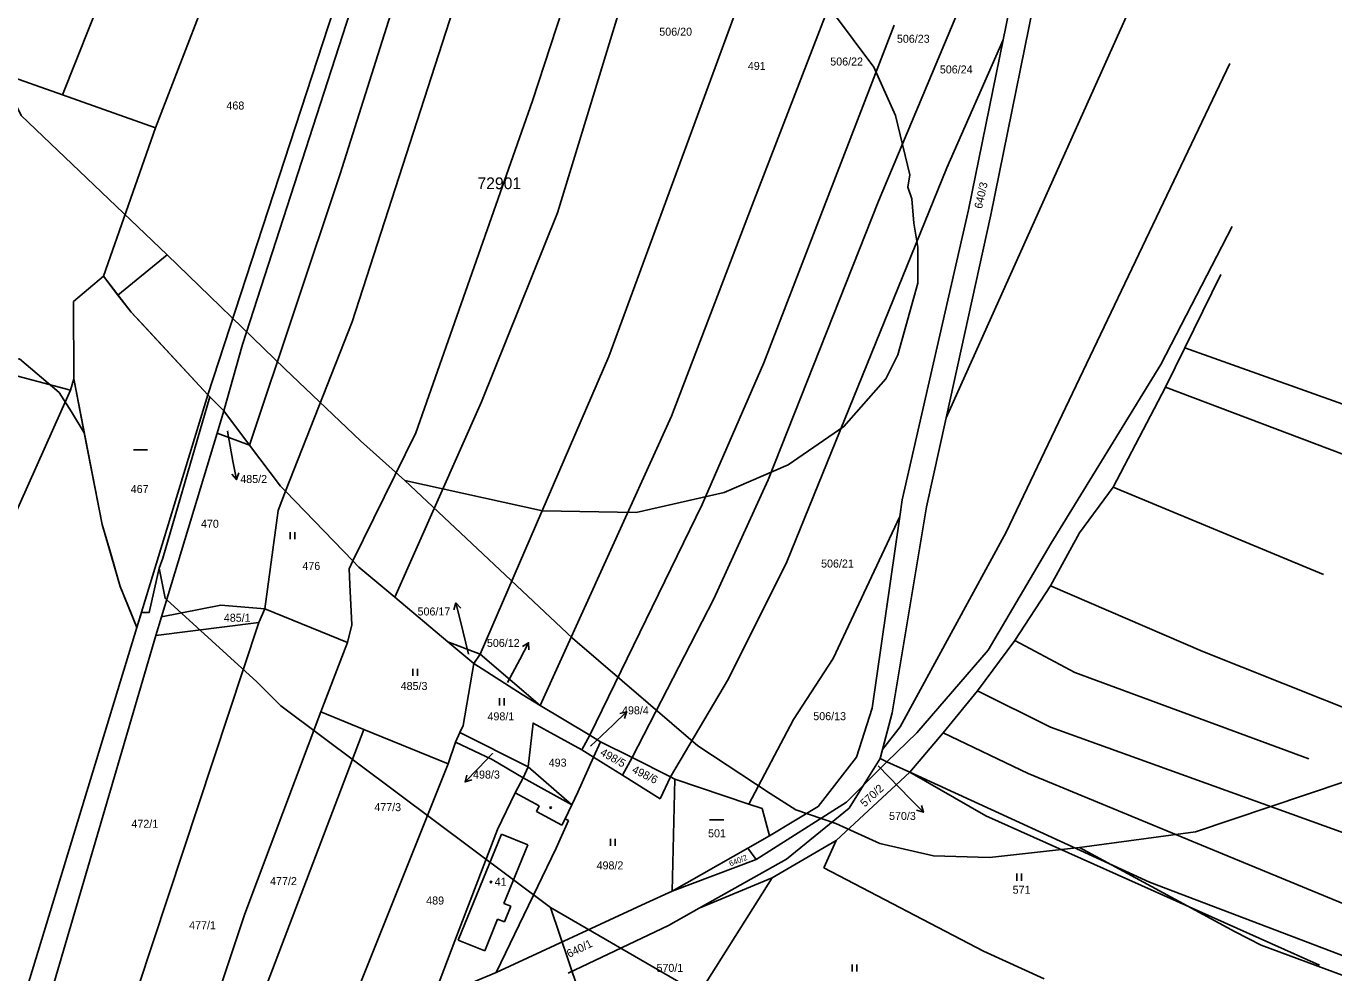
# Model space of a CAD drawing. Extents: x -743888 to -742027, y -1128394 to -1126768.
# Drawn here: x -742758.2 to -742480.3, y -1127090.1 to -1126888.9 of the extents above; entities that cross this region are included whole.
import ezdxf

# ---------------------------------------------------------------- set-up
doc = ezdxf.new("R2010")
doc.units = 0
for name, color, linetype in [('Vrstva 1', 7, 'Continuous'), ('Vrstva 16', 7, 'Continuous'), ('Vrstva 18', 7, 'Continuous'), ('Vrstva 19', 7, 'Continuous'), ('Vrstva 25', 7, 'Continuous'), ('Vrstva 3', 7, 'Continuous'), ('Vrstva 37', 7, 'Continuous'), ('Vrstva 4', 7, 'Continuous'), ('Vrstva 52', 7, 'Continuous'), ('Vrstva 53', 7, 'Continuous'), ('Vrstva 6', 7, 'Continuous')]:
    doc.layers.add(name, color=color, linetype=linetype)

msp = doc.modelspace()

# ---------------------------------------------------------------- linework, layer by layer
at = {"layer": 'Vrstva 1'}
for points in [[(-742550.57, -1126891.8), (-742539.32, -1126836.74)], [(-742553.22, -1126928.98), (-742541.56, -1126871.36)], [(-742557.96, -1126927.95), (-742550.57, -1126891.8)], [(-742572.06, -1126989.56), (-742557.96, -1126927.95)], [(-742562.72, -1126972.14), (-742553.22, -1126928.98)], [(-742748.16, -1126947.44), (-742741.76, -1126942.06)], [(-742741.76, -1126942.06), (-742735.91, -1126949.7)], [(-742748.16, -1126947.44), (-742748.07, -1126963.89)], [(-742735.91, -1126949.7), (-742719.6, -1126967.23)], [(-742748.07, -1126963.89), (-742742.04, -1126994.82)], [(-742734.68, -1127016.73), (-742719.6, -1126967.23)], [(-742719.6, -1126967.23), (-742716.17, -1126970.68)], [(-742717.6, -1126975.4), (-742716.17, -1126970.68)], [(-742716.17, -1126970.68), (-742710.71, -1126977.95)], [(-742566.88, -1126991.03), (-742562.72, -1126972.14)], [(-742729.41, -1127014.42), (-742717.6, -1126975.4)], [(-742710.71, -1126977.95), (-742704.16, -1126986.66)], [(-742704.16, -1126986.66), (-742703.1, -1126987.76)], [(-742703.1, -1126987.76), (-742688.81, -1127002.53)], [(-742572.58, -1126993.14), (-742572.06, -1126989.56)], [(-742574.16, -1127034.85), (-742566.88, -1126991.03)], [(-742742.04, -1126994.82), (-742738.19, -1127008)], [(-742578.46, -1127033.87), (-742572.58, -1126993.14)], [(-742688.81, -1127002.53), (-742687.53, -1127003.86)], [(-742687.53, -1127003.86), (-742679.87, -1127010.3)], [(-742738.19, -1127008), (-742734.68, -1127016.73)], [(-742679.87, -1127010.3), (-742668.63, -1127019.74)], [(-742730.63, -1127018.43), (-742729.41, -1127014.42)], [(-742781.25, -1127169.22), (-742734.68, -1127016.73)], [(-742737.64, -1127102.99), (-742708.78, -1127015.67)], [(-742753.9, -1127097.67), (-742730.63, -1127018.43)], [(-742668.63, -1127019.74), (-742663.1, -1127024.39)], [(-742663.1, -1127024.39), (-742652.83, -1127030.94)], [(-742652.83, -1127030.94), (-742648.95, -1127033.28)], [(-742648.95, -1127033.28), (-742638.43, -1127039.61)], [(-742581.78, -1127044.3), (-742578.46, -1127033.87)], [(-742576.22, -1127042.62), (-742574.16, -1127034.85)], [(-742651.5, -1127046.32), (-742650.49, -1127037.02), (-742640.1, -1127042.71)], [(-742638.43, -1127039.61), (-742636.14, -1127040.99)], [(-742668.53, -1127045.71), (-742666.98, -1127041.09)], [(-742666.98, -1127041.09), (-742659.18, -1127044.79)], [(-742637.62, -1127044.26), (-742636.14, -1127040.99)], [(-742636.14, -1127040.99), (-742629.44, -1127044.36)], [(-742659.18, -1127044.79), (-742652.6, -1127048.7)], [(-742641, -1127051.72), (-742637.62, -1127044.26)], [(-742640.1, -1127042.71), (-742637.62, -1127044.26)], [(-742637.62, -1127044.26), (-742631.47, -1127048.12)], [(-742631.47, -1127048.12), (-742629.44, -1127044.36)], [(-742629.44, -1127044.36), (-742621.26, -1127048.47)], [(-742589.93, -1127054.79), (-742581.78, -1127044.3)], [(-742580.29, -1127050.24), (-742576.74, -1127044.58)], [(-742576.74, -1127044.58), (-742576.22, -1127042.62)], [(-742576.74, -1127044.58), (-742575.31, -1127045.24)], [(-742575.31, -1127045.24), (-742570.42, -1127047.48)], [(-742692.49, -1127105.57), (-742668.53, -1127045.71)], [(-742652.6, -1127048.7), (-742651.5, -1127046.32)], [(-742570.42, -1127047.48), (-742519.53, -1127070.81)], [(-742654.28, -1127051.82), (-742652.6, -1127048.7)], [(-742621.26, -1127048.47), (-742620.33, -1127048.94)], [(-742620.96, -1127072.73), (-742620.33, -1127048.94)], [(-742620.33, -1127048.94), (-742604.64, -1127054.26)], [(-742583.33, -1127055.08), (-742580.29, -1127050.24)], [(-742658.01, -1127059.67), (-742654.28, -1127051.82)], [(-742642.23, -1127054.43), (-742641, -1127051.72)], [(-742643.7, -1127057.4), (-742642.23, -1127054.43)], [(-742604.64, -1127054.26), (-742601.82, -1127055.21)], [(-742601.82, -1127055.21), (-742600.22, -1127061)], [(-742600.22, -1127061), (-742589.93, -1127054.79)], [(-742596.61, -1127065.97), (-742583.33, -1127055.08)], [(-742645.55, -1127063.63), (-742642.98, -1127057.75)], [(-742643.7, -1127057.4), (-742642.98, -1127057.75)], [(-742667.08, -1127083.34), (-742658.01, -1127059.67)], [(-742604.82, -1127063.6), (-742600.22, -1127061)], [(-742658.33, -1127090.03), (-742645.55, -1127063.63)], [(-742620.96, -1127072.73), (-742604.82, -1127063.6)], [(-742604.82, -1127063.6), (-742603.07, -1127066.02)], [(-742603.07, -1127066.02), (-742620.96, -1127072.73)], [(-742615.18, -1127076.38), (-742596.61, -1127065.97)], [(-742626.53, -1127075.31), (-742620.96, -1127072.73)], [(-742519.53, -1127070.81), (-742452.64, -1127096.27)], [(-742658.33, -1127090.03), (-742626.53, -1127075.31)], [(-742621.7, -1127080.04), (-742615.18, -1127076.38)], [(-742643.05, -1127090.21), (-742621.7, -1127080.04)], [(-742671.78, -1127095.63), (-742667.08, -1127083.34)], [(-742663.55, -1127092.23), (-742658.33, -1127090.03)]]:
    msp.add_lwpolyline(points, dxfattribs=at)
at = {"layer": 'Vrstva 16'}
for p, q in [((-742713.02, -1126983.87), (-742713.51, -1126985.28)), ((-742667.31, -1127012.93), (-742666.89, -1127011.49)), ((-742652.71, -1127020.75), (-742651.44, -1127019.95)), ((-742632.06, -1127034.98), (-742630.6, -1127034.63)), ((-742663.49, -1127049.12), (-742664.93, -1127049.54)), ((-742567.92, -1127054.52), (-742567.55, -1127055.98))]:
    msp.add_line(p, q, dxfattribs=at)
for points in [[(-742715.45, -1126974.96), (-742714.25, -1126981.35)], [(-742714.25, -1126981.35), (-742713.51, -1126985.28), (-742714.49, -1126984.14)], [(-742665.94, -1127015.37), (-742666.89, -1127011.49), (-742665.85, -1127012.57)], [(-742664.21, -1127022.41), (-742665.94, -1127015.37)], [(-742653.31, -1127023.49), (-742651.44, -1127019.95), (-742651.39, -1127021.45)], [(-742655.92, -1127028.43), (-742653.31, -1127023.49)], [(-742633.5, -1127037.38), (-742630.6, -1127034.63), (-742631.03, -1127036.06)], [(-742638.3, -1127041.94), (-742633.5, -1127037.38)], [(-742659.09, -1127043.5), (-742662.15, -1127046.66)], [(-742662.15, -1127046.66), (-742664.93, -1127049.54), (-742664.57, -1127048.08)], [(-742577.15, -1127046.1), (-742570.34, -1127053.11)], [(-742570.34, -1127053.11), (-742567.55, -1127055.98), (-742569, -1127055.57)]]:
    msp.add_lwpolyline(points, dxfattribs=at)
at = {"layer": 'Vrstva 25'}
for p, q in [((-742735.42, -1126978.93), (-742732.42, -1126978.93)), ((-742702.1, -1126996.47), (-742702.1, -1126997.97)), ((-742701.1, -1126997.97), (-742701.1, -1126996.47)), ((-742676.04, -1127025.47), (-742676.04, -1127026.97)), ((-742675.04, -1127026.97), (-742675.04, -1127025.47)), ((-742657.62, -1127031.76), (-742657.62, -1127033.26)), ((-742656.62, -1127033.26), (-742656.62, -1127031.76)), ((-742612.97, -1127057.56), (-742609.97, -1127057.56)), ((-742634.03, -1127061.61), (-742634.03, -1127063.11)), ((-742633.03, -1127063.11), (-742633.03, -1127061.61)), ((-742547.68, -1127069.03), (-742547.68, -1127070.53)), ((-742546.68, -1127070.53), (-742546.68, -1127069.03)), ((-742582.66, -1127088.31), (-742582.66, -1127089.81)), ((-742581.66, -1127089.81), (-742581.66, -1127088.31))]:
    msp.add_line(p, q, dxfattribs=at)
for centre in [(-742646.76, -1127055.01), (-742659.41, -1127070.82)]:
    msp.add_circle(centre, 0.175, dxfattribs=at)
at = {"layer": 'Vrstva 3'}
for points in [[(-742666.37, -1127083.14), (-742657.21, -1127060.61)], [(-742657.21, -1127060.61), (-742651.6, -1127062.89)], [(-742656.67, -1127075.36), (-742651.6, -1127062.89)], [(-742656.67, -1127075.36), (-742655.24, -1127075.94)], [(-742656.59, -1127079.28), (-742655.24, -1127075.94)], [(-742660.76, -1127085.42), (-742658.03, -1127078.7)], [(-742658.03, -1127078.7), (-742656.59, -1127079.28)], [(-742666.37, -1127083.14), (-742660.76, -1127085.42)]]:
    msp.add_lwpolyline(points, dxfattribs=at)
at = {"layer": 'Vrstva 37'}
msp.add_circle((-742659.41, -1127070.82), 0.175, dxfattribs=at)
at = {"layer": 'Vrstva 4'}
for points in [[(-742652.6, -1127048.7), (-742642.23, -1127054.43)], [(-742654.28, -1127051.82), (-742649.19, -1127054.59)], [(-742649.73, -1127055.83), (-742649.19, -1127054.59)], [(-742649.73, -1127055.83), (-742644.34, -1127058.7)], [(-742644.34, -1127058.7), (-742643.7, -1127057.4)], [(-742666.37, -1127083.14), (-742657.21, -1127060.61)], [(-742657.21, -1127060.61), (-742651.6, -1127062.89)], [(-742656.67, -1127075.36), (-742651.6, -1127062.89)], [(-742656.67, -1127075.36), (-742655.24, -1127075.94)], [(-742656.59, -1127079.28), (-742655.24, -1127075.94)], [(-742660.76, -1127085.42), (-742658.03, -1127078.7)], [(-742658.03, -1127078.7), (-742656.59, -1127079.28)], [(-742666.37, -1127083.14), (-742660.76, -1127085.42)]]:
    msp.add_lwpolyline(points, dxfattribs=at)
at = {"layer": 'Vrstva 52'}
for points in [[(-742842.63, -1126818.77), (-742841.5, -1126820.88), (-742788.06, -1126876), (-742780, -1126884.88), (-742766.88, -1126897.63), (-742760.5, -1126905.25), (-742759.25, -1126907.88), (-742728.25, -1126937.5)], [(-742534.38, -1127063.5), (-742509.75, -1127060.13), (-742446.56, -1127038.88), (-742419, -1127033.38), (-742401.19, -1127030), (-742373.19, -1127022.75), (-742310.38, -1126996.88), (-742279.44, -1126979.13), (-742255.25, -1126963.88), (-742232.75, -1126946), (-742222.56, -1126935.88), (-742215.38, -1126928.13), (-742194.13, -1126902.75), (-742186.06, -1126890), (-742178.44, -1126877.25), (-742171.69, -1126862)], [(-742677.75, -1126985.5), (-742648.5, -1126991.88), (-742628.56, -1126992.25), (-742609.88, -1126988), (-742596.31, -1126982.13), (-742584.44, -1126974), (-742575.56, -1126963.88), (-742573, -1126958.75), (-742568.75, -1126943.5), (-742568.75, -1126935.88), (-742569.56, -1126930.75), (-742570, -1126925.63), (-742570.88, -1126923.13), (-742570.44, -1126920.5), (-742573.44, -1126907.88), (-742578.06, -1126897.63), (-742591.25, -1126879.88)], [(-743062.18, -1126930.43), (-743007.81, -1126932), (-742972.19, -1126931.63), (-742966.69, -1126932), (-742958.19, -1126931.63), (-742925.13, -1126931.13), (-742911.13, -1126930.25), (-742889.44, -1126930.75), (-742864, -1126931.13), (-742834.31, -1126932.38), (-742823.69, -1126934.13), (-742801.63, -1126940.13), (-742784.25, -1126946.38), (-742764.75, -1126955.38), (-742762.63, -1126960), (-742759.63, -1126959.63), (-742751.19, -1126966.75), (-742748.56, -1126970.88), (-742745.84, -1126975.32)], [(-742738.69, -1126946.07), (-742728.25, -1126937.5)], [(-742728.25, -1126937.5), (-742703.25, -1126961.75), (-742687.13, -1126977), (-742677.75, -1126985.5)], [(-742738.69, -1126946.07), (-742741.76, -1126942.06), (-742748.16, -1126947.44), (-742748.07, -1126963.89), (-742747.36, -1126967.52), (-742745.84, -1126975.32)], [(-742738.69, -1126946.07), (-742735.91, -1126949.7), (-742733.65, -1126952.13), (-742719.6, -1126967.23), (-742719.16, -1126967.67), (-742729.13, -1127002), (-742729.94, -1127004.13)], [(-742745.84, -1126975.32), (-742742.04, -1126994.82), (-742740.31, -1127000.74), (-742738.19, -1127008), (-742735.98, -1127013.5), (-742734.68, -1127016.73), (-742733.7, -1127013.5), (-742732.06, -1127013.5), (-742729.94, -1127004.13)], [(-742677.75, -1126985.5), (-742642.13, -1127019), (-742615.44, -1127041.88), (-742600.13, -1127052), (-742594.63, -1127055.5), (-742586.13, -1127058.38), (-742576.81, -1127062.63), (-742565.38, -1127065.25), (-742553.5, -1127065.63), (-742534.38, -1127063.5)], [(-742729.94, -1127004.13), (-742728.69, -1127010.5), (-742728.32, -1127010.83), (-742709.19, -1127028.25), (-742704.06, -1127033.38), (-742646.81, -1127076.25)], [(-742604.64, -1127054.26), (-742601.82, -1127055.21), (-742600.22, -1127061), (-742604.82, -1127063.6), (-742620.96, -1127072.73), (-742620.33, -1127048.94), (-742604.64, -1127054.26)], [(-742534.38, -1127063.5), (-742501.31, -1127081.38), (-742495.75, -1127084.25), (-742470.31, -1127093.63), (-742457.63, -1127097), (-742448.69, -1127099.63), (-742443.63, -1127100.88), (-742352.81, -1127132.25), (-742349.44, -1127134), (-742286.19, -1127157.75), (-742260.75, -1127166.63), (-742199.25, -1127187), (-742185.25, -1127192), (-742145.81, -1127205.25), (-742116.5, -1127212.38), (-742099.13, -1127215), (-742086.38, -1127216.25)], [(-742646.81, -1127076.25), (-742640.88, -1127093.63), (-742639.56, -1127114), (-742642.13, -1127136.88), (-742643.44, -1127139.5), (-742645.13, -1127154.75), (-742647.25, -1127164.88), (-742654.44, -1127183.63), (-742666.31, -1127208.13), (-742674.05, -1127219.73), (-742674.81, -1127220.88), (-742680.75, -1127227.25), (-742677.75, -1127229.38)], [(-742646.81, -1127076.25), (-742612.44, -1127096.13), (-742592.5, -1127106.38), (-742546.69, -1127126.75), (-742505.56, -1127139.5), (-742478.38, -1127150), (-742453.38, -1127158.5), (-742442.31, -1127163.63), (-742435.56, -1127165.75), (-742424.06, -1127170.88), (-742339.69, -1127206.5), (-742305.31, -1127215.88), (-742247.63, -1127232), (-742239.56, -1127234.88), (-742196.25, -1127246), (-742170.81, -1127254), (-742159.38, -1127257.38), (-742097.81, -1127270.5)]]:
    msp.add_lwpolyline(points, dxfattribs=at)
at = {"layer": 'Vrstva 6'}
for points in [[(-742603.91, -1126926.94), (-742554.63, -1126799.18)], [(-742691.49, -1126920.27), (-742659.71, -1126819.94)], [(-742688.91, -1126951.77), (-742648.33, -1126826.13)], [(-742634.42, -1126959.12), (-742587.89, -1126832.72)], [(-742750.49, -1126903.46), (-742732.76, -1126858.93)], [(-742562.72, -1126972.14), (-742511.64, -1126858.28)], [(-742730.7, -1126910.48), (-742713.83, -1126866.81)], [(-742650.59, -1126904.79), (-742637.92, -1126865.97)], [(-742577.05, -1126926.06), (-742554.59, -1126872.35)], [(-742719.6, -1126967.23), (-742690.51, -1126878.08)], [(-742712.23, -1126956.56), (-742687.03, -1126878.58)], [(-742645.29, -1126928.59), (-742630.66, -1126880.5)], [(-742601.46, -1126960.43), (-742573.73, -1126888.65)], [(-742562.56, -1126918.99), (-742550.57, -1126891.8)], [(-742549.96, -1126996.44), (-742502.42, -1126896.85)], [(-742763.27, -1126898.97), (-742750.49, -1126903.46)], [(-742750.49, -1126903.46), (-742730.7, -1126910.48)], [(-742675.39, -1126975.35), (-742650.59, -1126904.79)], [(-742741.76, -1126942.06), (-742730.7, -1126910.48)], [(-742596.53, -1127002.73), (-742562.56, -1126918.99)], [(-742710.71, -1126977.95), (-742691.49, -1126920.27)], [(-742661.43, -1126968.75), (-742645.29, -1126928.59)], [(-742621.1, -1126971.78), (-742603.91, -1126926.94)], [(-742600.55, -1126985.29), (-742577.05, -1126926.06)], [(-742517.1, -1126960.81), (-742501.91, -1126931.51)], [(-742512.02, -1126957.27), (-742504.35, -1126941.71)], [(-742703.1, -1126987.76), (-742688.91, -1126951.77)], [(-742716.17, -1126970.68), (-742712.23, -1126956.56)], [(-742661.75, -1127022.4), (-742634.42, -1126959.12)], [(-742516.09, -1126965.6), (-742512.02, -1126957.27)], [(-742512.02, -1126957.27), (-742426.6, -1126987.75)], [(-742614.56, -1126990.57), (-742601.46, -1126960.43)], [(-742540.36, -1126998.76), (-742517.1, -1126960.81)], [(-742763.72, -1126962.33), (-742748.81, -1126966.24)], [(-742748.81, -1126966.24), (-742748.07, -1126963.89)], [(-742763.25, -1126998.63), (-742748.81, -1126966.24)], [(-742527.24, -1126986.86), (-742516.09, -1126965.6)], [(-742516.09, -1126965.6), (-742463.84, -1126985.43)], [(-742679.87, -1127010.3), (-742661.43, -1126968.75)], [(-742648.95, -1127033.28), (-742621.1, -1126971.78)], [(-742717.6, -1126975.4), (-742710.71, -1126977.95)], [(-742688.81, -1127002.53), (-742675.39, -1126975.35)], [(-742612.06, -1127010.59), (-742600.55, -1126985.29)], [(-742534.38, -1126996.59), (-742527.24, -1126986.86)], [(-742527.24, -1126986.86), (-742482.52, -1127005.44)], [(-742704.66, -1126991.83), (-742703.1, -1126987.76)], [(-742707.46, -1127012.77), (-742704.66, -1126991.83)], [(-742638.43, -1127039.61), (-742614.56, -1126990.57)], [(-742586.73, -1127023.3), (-742572.58, -1126993.14)], [(-742572.46, -1127037.81), (-742549.96, -1126996.44)], [(-742540.51, -1127007.89), (-742534.38, -1126996.59)], [(-742553.75, -1127021.53), (-742540.36, -1126998.76)], [(-742689.59, -1127004.26), (-742688.81, -1127002.53)], [(-742608.98, -1127027.64), (-742596.53, -1127002.73)], [(-742689.59, -1127004.26), (-742689.43, -1127007.54)], [(-742689.43, -1127007.54), (-742689.01, -1127016.13)], [(-742548.14, -1127019.47), (-742540.51, -1127007.89)], [(-742540.51, -1127007.89), (-742508.14, -1127021.79)], [(-742729.41, -1127014.42), (-742716.86, -1127011.94)], [(-742716.86, -1127011.94), (-742707.46, -1127012.77)], [(-742629.44, -1127044.36), (-742612.06, -1127010.59)], [(-742708.78, -1127015.67), (-742707.46, -1127012.77)], [(-742707.46, -1127012.77), (-742689.92, -1127019.87)], [(-742730.63, -1127018.43), (-742708.78, -1127015.67)], [(-742689.92, -1127019.87), (-742689.01, -1127016.13)], [(-742690.78, -1127022.11), (-742689.92, -1127019.87)], [(-742668.63, -1127019.74), (-742661.75, -1127022.4)], [(-742556.03, -1127030.18), (-742548.14, -1127019.47)], [(-742548.14, -1127019.47), (-742535.36, -1127026.31)], [(-742695.58, -1127034.67), (-742690.78, -1127022.11)], [(-742663.1, -1127024.39), (-742661.75, -1127022.4)], [(-742661.75, -1127022.4), (-742648.95, -1127033.28)], [(-742568.92, -1127039.08), (-742553.75, -1127021.53)], [(-742508.14, -1127021.79), (-742465.67, -1127038.76)], [(-742665.33, -1127037.52), (-742663.1, -1127024.39)], [(-742595.13, -1127036.3), (-742586.73, -1127023.3)], [(-742621.26, -1127048.47), (-742608.98, -1127027.64)], [(-742535.36, -1127026.31), (-742485.61, -1127044.66)], [(-742563.37, -1127039.11), (-742556.03, -1127030.18)], [(-742556.03, -1127030.18), (-742540.54, -1127037.88)], [(-742711.74, -1127077.56), (-742695.58, -1127034.67)], [(-742695.58, -1127034.67), (-742686.48, -1127038.39)], [(-742604.64, -1127054.26), (-742595.13, -1127036.3)], [(-742719.74, -1127125.92), (-742686.48, -1127038.39)], [(-742686.48, -1127038.39), (-742668.53, -1127045.71)], [(-742666.98, -1127041.09), (-742666.02, -1127039.02)], [(-742666.02, -1127039.02), (-742665.33, -1127037.52)], [(-742666.02, -1127039.02), (-742651.5, -1127046.32)], [(-742640.1, -1127042.71), (-742638.43, -1127039.61)], [(-742576.22, -1127042.62), (-742572.46, -1127037.81)], [(-742575.31, -1127045.24), (-742568.92, -1127039.08)], [(-742570.42, -1127047.48), (-742563.37, -1127039.11)], [(-742563.37, -1127039.11), (-742545.28, -1127047.75)], [(-742540.54, -1127037.88), (-742464.14, -1127065.48)], [(-742580.29, -1127050.24), (-742575.31, -1127045.24)], [(-742651.5, -1127046.32), (-742642.23, -1127054.43)], [(-742586.05, -1127061.99), (-742570.42, -1127047.48)], [(-742570.42, -1127047.48), (-742554.29, -1127056.77)], [(-742545.28, -1127047.75), (-742507.28, -1127063.47)], [(-742631.47, -1127048.12), (-742623.51, -1127053.12)], [(-742623.51, -1127053.12), (-742621.26, -1127048.47)], [(-742583.91, -1127053.87), (-742580.29, -1127050.24)], [(-742603.07, -1127066.02), (-742583.91, -1127053.87)], [(-742554.29, -1127056.77), (-742483.35, -1127088.47)], [(-742599.65, -1127069.95), (-742586.05, -1127061.99)], [(-742588.7, -1127067.82), (-742586.05, -1127061.99)], [(-742507.28, -1127063.47), (-742474.83, -1127076.87)], [(-742617.44, -1127098.12), (-742599.65, -1127069.95)], [(-742615.18, -1127076.38), (-742599.65, -1127069.95)], [(-742588.7, -1127067.82), (-742554.78, -1127085.5)], [(-742731.14, -1127135.75), (-742711.74, -1127077.56)], [(-742554.78, -1127085.5), (-742541.89, -1127091.38)]]:
    msp.add_lwpolyline(points, dxfattribs=at)

# ---------------------------------------------------------------- texts
at = {"layer": 'Vrstva 16'}
for s, p in [('485/2', (-742712.7, -1126986)), ('506/17', (-742675.03, -1127014.16)), ('506/12', (-742660.29, -1127020.84)), ('498/4', (-742631.58, -1127035.17)), ('498/3', (-742663.23, -1127048.82)), ('570/3', (-742574.84, -1127057.62))]:
    msp.add_text(s, height=1.7, dxfattribs=at).set_placement(p)
at = {"layer": 'Vrstva 18'}
for s, height, p in [('506/20', 1.7, (-742623.66, -1126890.92)), ('506/23', 1.7, (-742573.17, -1126892.42)), ('491', 1.7, (-742604.85, -1126898.2)), ('506/22', 1.7, (-742587.33, -1126897.26)), ('506/24', 1.7, (-742564.05, -1126898.94)), ('468', 1.7, (-742715.64, -1126906.61)), ('485/2', 0.1, (-742715.45, -1126974.96)), ('467', 1.7, (-742735.98, -1126988.12)), ('470', 1.7, (-742721.05, -1126995.51)), ('476', 1.7, (-742699.5, -1127004.47)), ('506/21', 1.7, (-742589.28, -1127003.97)), ('485/1', 1.7, (-742716.19, -1127015.49)), ('506/17', 0.1, (-742664.21, -1127022.41)), ('485/3', 1.7, (-742678.62, -1127029.99)), ('506/12', 0.1, (-742655.92, -1127028.43)), ('498/1', 1.7, (-742660.17, -1127036.45)), ('506/13', 1.7, (-742590.94, -1127036.41)), ('498/4', 0.1, (-742638.3, -1127041.94)), ('498/3', 0.1, (-742659.09, -1127043.5)), ('493', 1.7, (-742647.16, -1127046.28)), ('570/3', 0.1, (-742577.15, -1127046.1)), ('477/3', 1.7, (-742684.22, -1127055.75)), ('472/1', 1.7, (-742735.83, -1127059.28)), ('501', 1.7, (-742613.3, -1127061.31)), ('498/2', 1.7, (-742636.99, -1127068.13)), ('477/2', 1.7, (-742706.36, -1127071.46)), ('571', 1.7, (-742548.58, -1127073.3)), ('489', 1.7, (-742673.19, -1127075.59)), ('477/1', 1.7, (-742723.56, -1127080.84)), ('570/1', 1.7, (-742624.26, -1127089.91))]:
    msp.add_text(s, height=height, dxfattribs=at).set_placement(p)
for s, height, rotation, p in [('640/3', 1.7, 77.3738, (-742555.1, -1126927.81)), ('498/5', 1.7, 330.8107, (-742636.38, -1127043.75)), ('498/6', 1.7, 333.3994, (-742629.61, -1127047.46)), ('570/2', 1.7, 42.4471, (-742580.02, -1127054.98)), ('640/2', 1.19, 22.1514, (-742608.53, -1127067.54)), ('640/1', 1.7, 25.8512, (-742642.83, -1127086.95))]:
    msp.add_text(s, height=height, rotation=rotation, dxfattribs=at).set_placement(p)
at = {"layer": 'Vrstva 19'}
msp.add_text('41', height=1.7, dxfattribs=at).set_placement((-742658.66, -1127071.61))
at = {"layer": 'Vrstva 53'}
msp.add_text('72901', height=2.5, dxfattribs=at).set_placement((-742662.31, -1126923.54))

doc.saveas('drawing.dxf')
